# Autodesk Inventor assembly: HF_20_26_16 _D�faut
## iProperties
Created: 2011-01
Part Number: HF_20_26_16 _D�faut
Document SubType Name: Assembly
Designer: eric
Mass: 2.78295 g
Surface Area: 53.1486 cm^2
Volume: 2.78295 cm^3
Density: 1 g/cm^3
Author: eric
